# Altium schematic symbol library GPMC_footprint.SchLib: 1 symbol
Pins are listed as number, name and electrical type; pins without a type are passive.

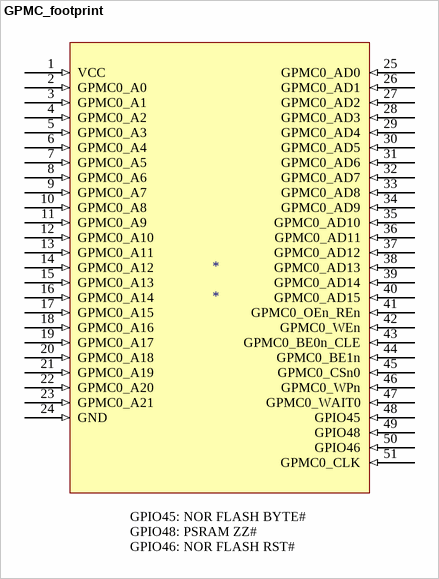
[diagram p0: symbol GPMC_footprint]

## GPMC_footprint
designator *
pins: 1 VCC (in), 2 GPMC0_A0 (in) "GPMC Address 0", 3 GPMC0_A1 (in) "GPMC Address 1", 4 GPMC0_A2 (in) "GPMC Address 2", 5 GPMC0_A3 (in) "GPMC Address 3", 6 GPMC0_A4 (in) "GPMC Address 4", 7 GPMC0_A5 (in) "GPMC Address 5", 8 GPMC0_A6 (in) "GPMC Address 6", 9 GPMC0_A7 (in) "GPMC Address 7", 10 GPMC0_A8 (in) "GPMC Address 8", 11 GPMC0_A9 (in) "GPMC Address 9", 12 GPMC0_A10 (in) "GPMC Address 10", 13 GPMC0_A11 (in) "GPMC Address 11", 14 GPMC0_A12 (in) "GPMC Address 12", 15 GPMC0_A13 (in) "GPMC Address 13", 16 GPMC0_A14 (in) "GPMC Address 14", 17 GPMC0_A15 (in) "GPMC Address 15", 18 GPMC0_A16 (in) "GPMC Address 16", 19 GPMC0_A17 (in) "GPMC Address 17", 20 GPMC0_A18 (in) "GPMC Address 18", 21 GPMC0_A19 (in) "GPMC Address 19", 22 GPMC0_A20 (in) "GPMC Address 20", 23 GPMC0_A21 (in) "GPMC Address 21", 24 GND (in), 25 GPMC0_AD0 (in) "GPMC Data 0", 26 GPMC0_AD1 (in) "GPMC Data 1", 27 GPMC0_AD2 (in) "GPMC Data 2", 28 GPMC0_AD3 (in) "GPMC Data 3", 29 GPMC0_AD4 (in) "GPMC Data 4", 30 GPMC0_AD5 (in) "GPMC Data 5", 31 GPMC0_AD6 (in) "GPMC Data 6", 32 GPMC0_AD7 (in) "GPMC Data 7", 33 GPMC0_AD8 (in) "GPMC Data 8", 34 GPMC0_AD9 (in) "GPMC Data 9", 35 GPMC0_AD10 (in) "GPMC Data 10", 36 GPMC0_AD11 (in) "GPMC Data 11", 37 GPMC0_AD12 (in) "GPMC Data 12", 38 GPMC0_AD13 (in) "GPMC Data 13", 39 GPMC0_AD14 (in) "GPMC Data 14", 40 GPMC0_AD15 (in) "GPMC Data 15", 41 GPMC0_OEn_REn (in) "GPMC Output Enable (active low) or Read Enable (active low)", 42 GPMC0_WEn (in) "GPMC Write Enable (active low)", 43 GPMC0_BE0n_CLE (in) "GPMC Lower-Byte Enable (active low)", 44 GPMC0_BE1n (in) "GPMC Upper-Byte Enable (active low)", 45 GPMC0_CSn0 (in) "GPMC Chip Select 0 (active low)", 46 GPMC0_WPn (in) "GPMC Flash Write Protect", 47 GPMC0_WAIT0 (in) "GPMC External Indication of Wait", 48 GPIO45 (in) "BYTE# on NOR FLASH", 49 GPIO48 (in) "ZZ# on PSRAM", 50 GPIO46 (in) "RST# on NOR FLASH", 51 GPMC0_CLK (in)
